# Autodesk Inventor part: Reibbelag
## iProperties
Shininess: 20.0
Angle Display Precision: 2
Document Length Units: 11269
Document Angle Units: 11279
Document Time Units: 11290
Document Mass Units: 11283
Document Length Units Precision: 3
Document Angle Units Precision: 2
Created: 2003-02
Part Number: Reibbelag
Material: ABS Plastik
Document SubType Name: Modellieren
Designer: Administrator
Density: 0.0
Volumn: 0.0
Area: 0.0
PropertySet Name: Model Information
Control State: 0
Master: False
Checked Out: False
Author: Administrator
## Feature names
1. Grundkörper [Extrusion]
